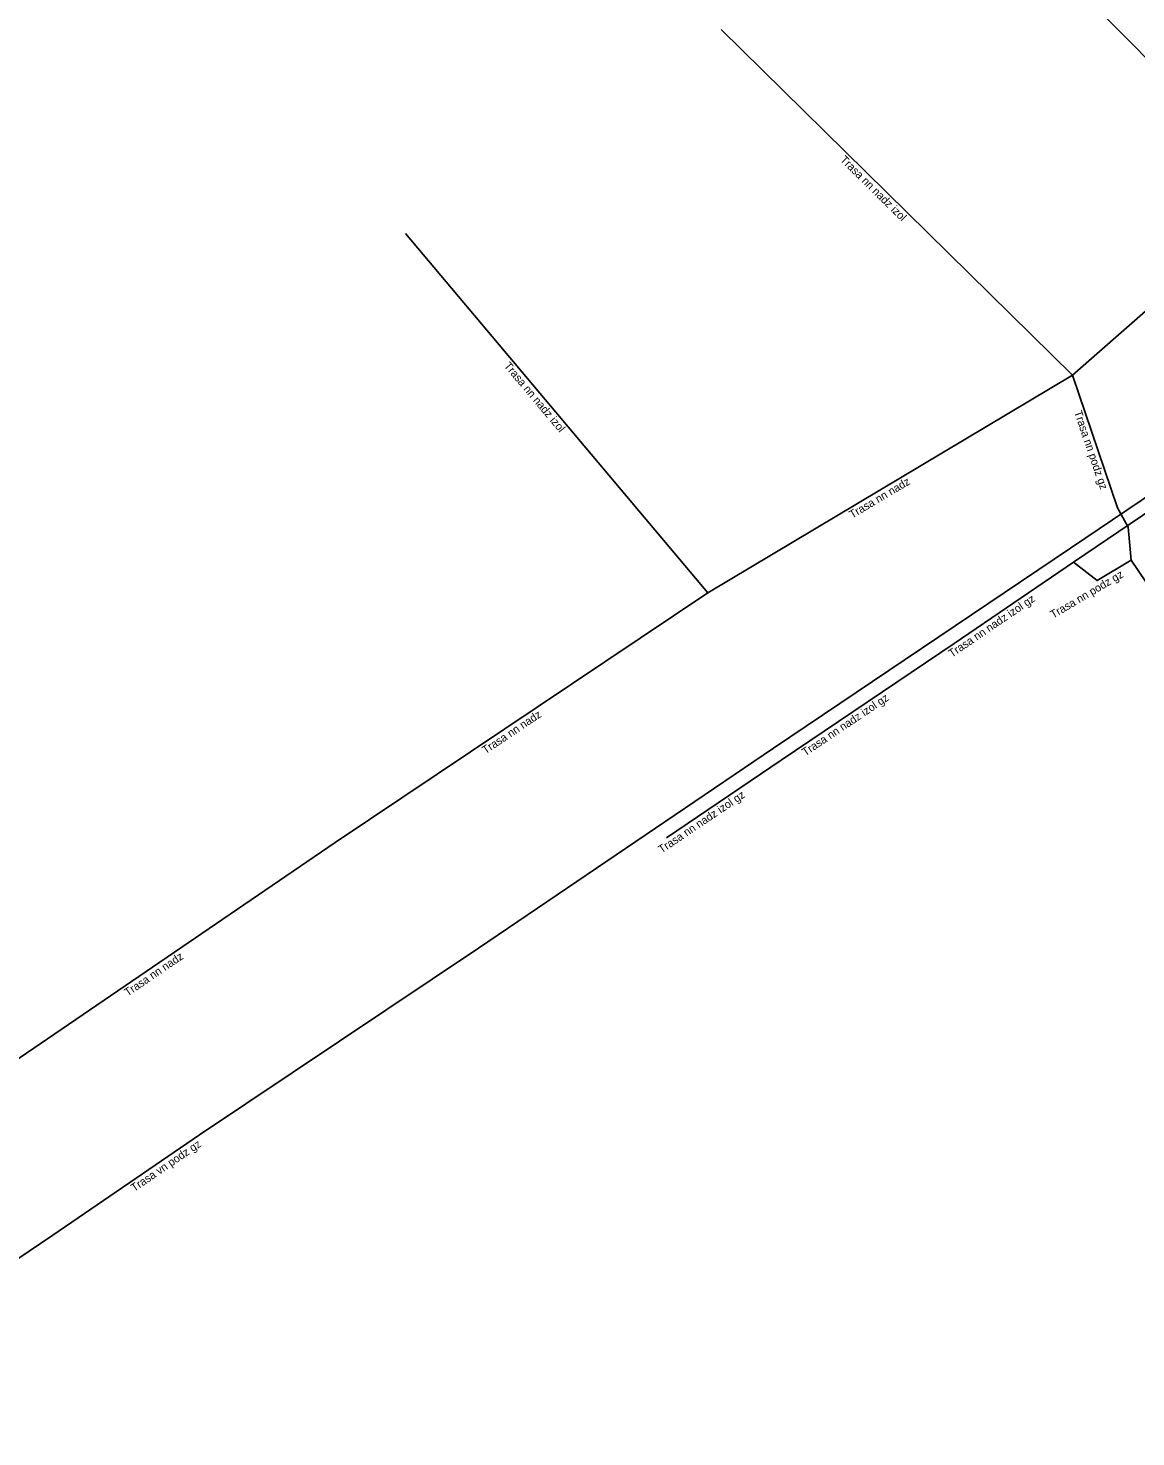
# Model space of a CAD drawing. Extents: x -468149 to -467677, y -1100197 to -1099840.
# Drawn here: x -467931 to -467861.8, y -1100014 to -1099925.9 of the extents above; entities that cross this region are included whole.
import ezdxf

# ---------------------------------------------------------------- set-up
doc = ezdxf.new("R2010")
doc.units = 0
for name, color, linetype in [('Popiskový text - Ostatní atributy Trasy', 7, 'Continuous'), ('Spojnice NN', 7, 'Continuous'), ('Spojnice VN', 7, 'Continuous')]:
    doc.layers.add(name, color=color, linetype=linetype)

msp = doc.modelspace()

# ---------------------------------------------------------------- linework, layer by layer
at = {"layer": 'Spojnice NN'}
for points in [[(-467887.694, -1099926.016), (-467865.757, -1099947.633)], [(-467865.757, -1099947.633), (-467852.759, -1099936.229)], [(-467834.288, -1099938.069), (-467865.684, -1099959.314)], [(-467907.42, -1099938.779), (-467888.542, -1099961.22)], [(-467865.757, -1099947.633), (-467888.542, -1099961.22)], [(-467862.08, -1099959.19), (-467862.28, -1099957.13), (-467862.94, -1099955.91), (-467865.757, -1099947.633)], [(-467865.684, -1099959.314), (-467873.141, -1099964.394)], [(-467862.08, -1099959.19), (-467864.213, -1099960.457), (-467865.684, -1099959.314)], [(-467825.34, -1100004.08), (-467830.31, -1100006.51), (-467838.14, -1099995.5), (-467844.86, -1099985.77), (-467848.16, -1099979.92), (-467853.15, -1099972.38), (-467862.08, -1099959.19)], [(-467888.542, -1099961.22), (-467911.814, -1099976.83)], [(-467873.141, -1099964.394), (-467883.961, -1099971.684)], [(-467883.961, -1099971.684), (-467891.109, -1099976.523)], [(-467911.814, -1099976.83), (-467933.282, -1099991.465)]]:
    msp.add_lwpolyline(points, dxfattribs=at)
at = {"layer": 'Spojnice VN'}
for points in [[(-467852.759, -1099936.229), (-467928.719, -1099859.979)], [(-467819.86, -1099965.54), (-467821.51, -1099966.51), (-467823.432, -1099967.663), (-467823.75, -1099967.32), (-467825.19, -1099964.98), (-467826.38, -1099964.52), (-467831.38, -1099967.51), (-467831.77, -1099967.36), (-467832.58, -1099965.53), (-467836.31, -1099959.48), (-467844.64, -1099946.99), (-467846.96, -1099946.34), (-467847.92, -1099946.47), (-467849.12, -1099947.12), (-467865.88, -1099958.44), (-467884.43, -1099970.92), (-467902.87, -1099983.43), (-467920.29, -1099995.09), (-467929.47, -1100001.36), (-467948.11, -1100013.96)]]:
    msp.add_lwpolyline(points, dxfattribs=at)

# ---------------------------------------------------------------- texts
at = {"layer": 'Popiskový text - Ostatní atributy Trasy'}
for s, rotation, p in [('Trasa nn nadz izol', 315.42228, (-467880.309, -1099934.206)), ('Trasa nn nadz izol', 310.07043, (-467901.304, -1099947.059)), ('Trasa nn podz gz', 288.79602, (-467865.661, -1099949.93)), ('Trasa nn nadz', 30.80939, (-467879.52, -1099956.597)), ('Trasa nn podz gz', 30.70034, (-467866.963, -1099962.846)), ('Trasa nn nadz izol gz', 34.26029, (-467873.291, -1099965.282)), ('Trasa nn nadz izol gz', 33.97112, (-467882.447, -1099971.447)), ('Trasa nn nadz', 33.85225, (-467902.43, -1099971.318)), ('Trasa nn nadz izol gz', 34.09874, (-467891.424, -1099977.521)), ('Trasa nn nadz', 34.28274, (-467924.783, -1099986.458)), ('Trasa vn podz gz', 34.33333, (-467924.373, -1099998.666))]:
    msp.add_text(s, height=0.5, rotation=rotation, dxfattribs=at).set_placement(p)

doc.saveas('drawing.dxf')
